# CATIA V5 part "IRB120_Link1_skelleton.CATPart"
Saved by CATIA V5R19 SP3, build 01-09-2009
Part number: IRB120_Link1_skelleton
Bounding box of the stored display mesh (mm): x 0 to 0, y -65 to 0, z 0 to 290
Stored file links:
  Z:\Projects\ABB_Robotics\ABB LIB\V5\V5PARTS\ABB\120\IRB120_Link1_skelleton.CATPart
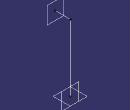
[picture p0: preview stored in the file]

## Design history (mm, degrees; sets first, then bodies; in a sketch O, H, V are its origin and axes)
Body1 (main body)
  Line1: type PtPt, FirstPoint {point type Coord, X 0, Y 0, Z 0}, SecondPoint {point type Coord, X 0, Y 0, Z 290, RefPoint {point type Coord, X 0, Y 0, Z 0}}
  Point1: (150, 0, 0), relative to vertex of Line1
  Line2: type PtPt, FirstPoint vertex of Line1, SecondPoint {point type Coord, X 0, Y -65, Z 0, RefPoint vertex of Line1}
  Plane1: type OffsetPt, RefPlane zx-plane, RefPoint vertex of Line2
